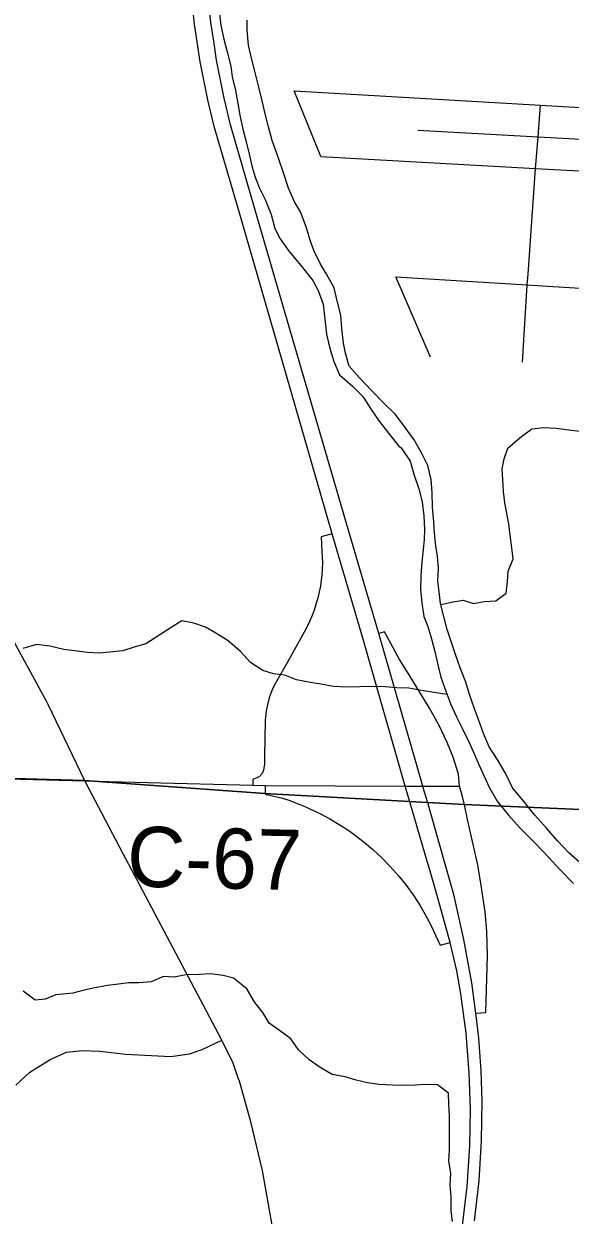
# Model space of a CAD drawing. Extents: x 0 to 34, y 0 to 22.
# Drawn here: x 4.264 to 4.779, y 17.887 to 19.012 of the extents above; entities that cross this region are included whole.
import ezdxf

# ---------------------------------------------------------------- set-up
doc = ezdxf.new("R2010")
doc.units = 0
for name, color, linetype in [('GM_X_City_Street', 7, 'Continuous'), ('GM_X_Corporation', 7, 'Continuous'), ('GM_X_County_Road', 7, 'Continuous'), ('GM_X_County_Road_Text', 7, 'Continuous'), ('GM_X_Interchange_Ramps', 7, 'Continuous'), ('GM_X_Major_River', 7, 'Continuous'), ('GM_X_Minor_River', 7, 'Continuous'), ('GM_X_State_Route', 7, 'Continuous'), ('GM_X_Township_Road', 7, 'Continuous')]:
    doc.layers.add(name, color=color, linetype=linetype)

msp = doc.modelspace()

# ---------------------------------------------------------------- linework, layer by layer
at = {"layer": 'GM_X_City_Street'}
msp.add_lwpolyline([(4.2563, 18.0102), (4.2697, 18.0224), (4.2887, 18.0346), (4.3043, 18.0414), (4.3196, 18.043), (4.3358, 18.0423), (4.36, 18.0395), (4.4028, 18.0374), (4.4204, 18.0399), (4.4321, 18.044), (4.4507, 18.0526)], dxfattribs=at)
at = {"layer": 'GM_X_Corporation'}
for points in [[(8.9341, 20.0965), (4.0253, 20.0965), (4.0048, 19.6179), (3.9989, 19.4811), (3.9958, 19.4084), (3.9927, 19.3361), (3.985, 19.1554), (3.9815, 19.0743), (3.9811, 19.0651), (3.9791, 19.0203), (3.9633, 18.6757), (3.9621, 18.6649), (3.9605, 18.6483), (3.9468, 18.3161), (3.9995, 18.3123), (4.1878, 18.3016), (4.3213, 18.298), (4.4914, 18.2857), (4.6278, 18.2782), (4.6446, 18.2772), (4.6794, 18.2753), (5.2805, 18.2495)], [(5.2805, 18.2495), (4.6794, 18.2753), (4.6446, 18.2772), (4.6278, 18.2782), (4.4914, 18.2857), (4.3213, 18.298), (4.1878, 18.3016), (3.9995, 18.3123), (3.9468, 18.3161), (3.9184, 17.601), (3.9153, 17.5377), (3.8996, 17.2129), (3.8967, 17.1525), (3.8962, 17.1422), (3.892, 17.0557), (3.8892, 16.9991), (3.8746, 16.7014), (3.8519, 16.2289), (3.8392, 15.9277), (3.8357, 15.8507), (3.8186, 15.5835)]]:
    msp.add_lwpolyline(points, dxfattribs=at)
at = {"layer": 'GM_X_County_Road'}
for p, q in [((4.3215, 18.2975), (4.2869, 18.3697)), ((4.3215, 18.2975), (4.3314, 18.2972)), ((4.3314, 18.2972), (4.3809, 18.296)), ((4.6472, 18.2924), (4.6611, 18.2924)), ((4.6611, 18.2924), (4.675, 18.2924))]:
    msp.add_line(p, q, dxfattribs=at)
for points in [[(4.2869, 18.3697), (4.286, 18.3715), (4.2515, 18.4352), (4.224, 18.4898), (4.2171, 18.5041), (4.2112, 18.5231), (4.2021, 18.5636), (4.201, 18.5798), (4.2016, 18.5981), (4.2027, 18.6147), (4.206, 18.6517), (4.2118, 18.803), (4.215, 18.8563), (4.2189, 18.9177), (4.2238, 18.9634), (4.2326, 19.0308), (4.2343, 19.0415)], [(4.0601, 18.3083), (4.188, 18.301), (4.3215, 18.2975)], [(4.3762, 18.1938), (4.3578, 18.2287), (4.3215, 18.2975)], [(4.3809, 18.296), (4.4801, 18.2934), (4.4917, 18.2932), (4.6236, 18.2925), (4.6403, 18.2924), (4.6472, 18.2924)], [(4.4663, 18.0168), (4.4614, 18.0309), (4.4507, 18.0526), (4.3762, 18.1938)], [(4.5078, 17.8236), (4.5074, 17.8265), (4.489, 17.9296), (4.478, 17.9757), (4.4673, 18.014), (4.4663, 18.0168)]]:
    msp.add_lwpolyline(points, dxfattribs=at)
at = {"layer": 'GM_X_Interchange_Ramps'}
for p, q in [((4.5549, 18.5309), (4.5444, 18.5279)), ((4.692, 18.2194), (4.6826, 18.2612))]:
    msp.add_line(p, q, dxfattribs=at)
for points in [[(4.5444, 18.5279), (4.5452, 18.514), (4.5455, 18.509), (4.5456, 18.5036), (4.5454, 18.4976), (4.545, 18.4918), (4.5445, 18.487), (4.5437, 18.4814), (4.5426, 18.4759), (4.5412, 18.4701), (4.5398, 18.4652), (4.5378, 18.4588), (4.5358, 18.4536), (4.5338, 18.4488), (4.5311, 18.4433), (4.5283, 18.4379), (4.5126, 18.4097)], [(4.6668, 18.3252), (4.6633, 18.3337), (4.6558, 18.3498), (4.6467, 18.3663), (4.6276, 18.3977), (4.6183, 18.4123), (4.6042, 18.4382), (4.5988, 18.4367)], [(4.5126, 18.4097), (4.504, 18.3943), (4.5014, 18.3897), (4.499, 18.385), (4.4971, 18.3805), (4.4955, 18.376), (4.494, 18.3706), (4.4929, 18.3652), (4.4923, 18.3609), (4.4919, 18.3576), (4.4917, 18.3544), (4.491, 18.3211), (4.4909, 18.3137), (4.4901, 18.3077), (4.4887, 18.3045), (4.4859, 18.3013), (4.4801, 18.2989), (4.4801, 18.2934)], [(4.675, 18.2924), (4.6741, 18.3039), (4.669, 18.3199), (4.6668, 18.3252)], [(4.4917, 18.2932), (4.4917, 18.2851), (4.5081, 18.2812), (4.5149, 18.2789), (4.5235, 18.2757), (4.5245, 18.2753)], [(4.6826, 18.2612), (4.6796, 18.2748), (4.6777, 18.2827), (4.675, 18.2924)], [(4.5245, 18.2753), (4.5332, 18.2716), (4.5439, 18.2664), (4.5525, 18.2618), (4.5614, 18.2565), (4.5704, 18.2507), (4.5781, 18.2451), (4.5854, 18.2394), (4.5933, 18.2326), (4.6018, 18.2248), (4.6098, 18.2165), (4.6176, 18.2076), (4.6245, 18.199), (4.6318, 18.1889), (4.6375, 18.1801), (4.6438, 18.1692), (4.6483, 18.1606), (4.6566, 18.1425), (4.6661, 18.1448)], [(4.6902, 18.0781), (4.6998, 18.0788), (4.7012, 18.1326), (4.7008, 18.1556), (4.6992, 18.1735), (4.6956, 18.1969), (4.6922, 18.2183), (4.692, 18.2194)]]:
    msp.add_lwpolyline(points, dxfattribs=at)
at = {"layer": 'GM_X_Major_River'}
for points in [[(4.4478, 19.0273), (4.4497, 19.0109), (4.4525, 18.998), (4.4557, 18.9861), (4.4592, 18.9724), (4.4605, 18.9625), (4.4637, 18.9495), (4.4657, 18.9373), (4.4677, 18.9263), (4.4705, 18.913), (4.4733, 18.9023), (4.4768, 18.8882), (4.4793, 18.8771), (4.4821, 18.8675), (4.4861, 18.858), (4.4915, 18.8465), (4.4973, 18.8323), (4.5008, 18.8193), (4.5059, 18.8094), (4.5144, 18.7974), (4.5255, 18.7839), (4.5366, 18.77), (4.5417, 18.7605), (4.5464, 18.7478), (4.548, 18.7334), (4.5496, 18.7193), (4.5524, 18.7071), (4.5563, 18.6937), (4.5617, 18.6811), (4.574, 18.6702), (4.5841, 18.6601), (4.5903, 18.6502), (4.5991, 18.6371), (4.608, 18.6259), (4.6176, 18.6135)], [(4.7912, 18.2179), (4.7782, 18.2296), (4.7674, 18.2408), (4.757, 18.2528), (4.7459, 18.2651), (4.7363, 18.2775), (4.7248, 18.291), (4.719, 18.3036), (4.711, 18.3171), (4.7029, 18.3298), (4.6974, 18.3424), (4.6928, 18.3554), (4.6888, 18.3665), (4.6845, 18.3791), (4.681, 18.3909), (4.6756, 18.4043), (4.6713, 18.4169), (4.6677, 18.4273), (4.6634, 18.4406), (4.6571, 18.4651), (4.6558, 18.4761), (4.6545, 18.486), (4.6551, 18.4981), (4.6542, 18.5096), (4.6525, 18.5195), (4.6512, 18.5316), (4.6507, 18.5423), (4.6494, 18.556), (4.649, 18.5697), (4.6481, 18.5822), (4.6449, 18.5952), (4.6387, 18.6078), (4.6322, 18.6197), (4.6237, 18.6313), (4.6144, 18.6436), (4.6029, 18.6548), (4.5918, 18.6661), (4.5806, 18.6781), (4.571, 18.6893), (4.5675, 18.7015), (4.5654, 18.711), (4.5638, 18.7247), (4.5629, 18.7373), (4.5594, 18.751), (4.5566, 18.7632), (4.5496, 18.7759), (4.5434, 18.7862), (4.5376, 18.7985), (4.534, 18.8081), (4.5304, 18.8207), (4.525, 18.8348), (4.5192, 18.8444), (4.5137, 18.8571), (4.5091, 18.8708), (4.5041, 18.8857), (4.4983, 18.9022), (4.4948, 18.9151), (4.492, 18.9262), (4.4889, 18.9396), (4.4861, 18.9514), (4.4822, 18.9666), (4.4787, 18.98), (4.4759, 18.9922), (4.4747, 19.0063), (4.4745, 19.0158)], [(4.6176, 18.6135), (4.6199, 18.612), (4.6283, 18.5993), (4.6322, 18.5863), (4.6365, 18.5733), (4.6397, 18.5611), (4.6413, 18.5478), (4.6418, 18.5349), (4.6416, 18.5254), (4.6407, 18.5159), (4.6393, 18.5041), (4.6383, 18.4913), (4.638, 18.4784), (4.6393, 18.4658), (4.6413, 18.4528), (4.6449, 18.4433), (4.6485, 18.4318), (4.6516, 18.4196), (4.6547, 18.4059), (4.6572, 18.3956), (4.6619, 18.3822), (4.6669, 18.3696), (4.672, 18.3581), (4.6775, 18.3473), (4.684, 18.3339), (4.6891, 18.3224), (4.6931, 18.3129), (4.6974, 18.3033), (4.7032, 18.291), (4.7106, 18.2783), (4.7209, 18.2656), (4.7324, 18.2525), (4.7465, 18.2385), (4.7588, 18.2254), (4.7699, 18.2134), (4.7825, 18.2006)]]:
    msp.add_lwpolyline(points, dxfattribs=at)
at = {"layer": 'GM_X_Minor_River'}
for points in [[(4.6573, 18.4641), (4.6688, 18.4665), (4.6783, 18.4682), (4.6881, 18.465), (4.6983, 18.4668), (4.7093, 18.4674), (4.7189, 18.4748), (4.7202, 18.4859), (4.7207, 18.4957), (4.7254, 18.5071), (4.7244, 18.5177), (4.7227, 18.5295), (4.7213, 18.5402), (4.7178, 18.56), (4.7164, 18.5707), (4.7158, 18.5821), (4.7152, 18.5923), (4.7169, 18.6018), (4.7204, 18.6116), (4.7319, 18.6214), (4.743, 18.6299), (4.754, 18.6313), (4.7661, 18.6307), (4.7782, 18.629), (4.7885, 18.6277)], [(4.663, 18.3792), (4.6528, 18.3808), (4.6411, 18.3825), (4.6271, 18.385), (4.6157, 18.3855), (4.6048, 18.3865), (4.5945, 18.3866), (4.5809, 18.3864), (4.5691, 18.3859), (4.5562, 18.3868), (4.5441, 18.3889), (4.5343, 18.3905), (4.5211, 18.393), (4.5101, 18.3974), (4.4995, 18.3987), (4.4894, 18.4019), (4.4777, 18.4093), (4.4684, 18.4197), (4.4568, 18.4297), (4.4451, 18.4371), (4.4353, 18.4426), (4.4244, 18.4465), (4.413, 18.4486), (4.402, 18.4419), (4.379, 18.4271), (4.3691, 18.4242), (4.3573, 18.4202), (4.3452, 18.4192), (4.3349, 18.4182), (4.3239, 18.4188), (4.3118, 18.4205), (4.3016, 18.4217), (4.2884, 18.4246), (4.2759, 18.4263), (4.263, 18.4227)], [(4.6672, 17.9048), (4.6662, 17.9162), (4.6667, 17.9268), (4.665, 17.9386), (4.6655, 17.9489), (4.6656, 17.9595), (4.6654, 17.9705), (4.6656, 17.9808), (4.665, 17.9922), (4.6647, 18.0028), (4.6542, 18.0106), (4.6428, 18.0108), (4.633, 18.0102), (4.6224, 18.0099), (4.6118, 18.0101), (4.5992, 18.0107), (4.5883, 18.0123), (4.5773, 18.0148), (4.5671, 18.018), (4.5547, 18.0204), (4.5426, 18.0275), (4.5329, 18.0344), (4.5231, 18.0437), (4.5157, 18.0541), (4.5052, 18.0618), (4.4954, 18.0688), (4.4895, 18.0788), (4.482, 18.0884), (4.4743, 18.1011), (4.4619, 18.1111), (4.4521, 18.1139), (4.44, 18.1153), (4.4297, 18.1147), (4.4168, 18.1145), (4.4058, 18.1123), (4.3956, 18.1129), (4.3841, 18.1077), (4.3724, 18.1068), (4.3629, 18.1069), (4.3534, 18.1055), (4.3428, 18.1042), (4.3295, 18.1017), (4.3196, 18.0996), (4.3101, 18.097), (4.2941, 18.0954), (4.2842, 18.0914), (4.2747, 18.0904), (4.2635, 18.0989)], [(4.6684, 17.8815), (4.667, 17.8918), (4.6672, 17.9048)]]:
    msp.add_lwpolyline(points, dxfattribs=at)
at = {"layer": 'GM_X_State_Route'}
for points in [[(4.5549, 18.5309), (4.5111, 18.6826), (4.4664, 18.837), (4.4436, 18.9155), (4.4376, 18.9407), (4.4304, 18.9765), (4.4251, 19.0122), (4.4218, 19.0409), (4.4203, 19.0712), (4.4194, 19.0958), (4.4194, 19.1245), (4.4201, 19.1598), (4.4341, 19.416), (4.4387, 19.5226), (4.4504, 19.7346), (4.453, 19.8068), (4.4508, 19.8691), (4.4482, 19.9018)], [(4.4431, 18.9959), (4.4405, 19.0138), (4.4372, 19.0426), (4.4357, 19.0728), (4.4348, 19.0974), (4.4348, 19.1261), (4.4372, 19.1632), (4.4373, 19.1652), (4.4439, 19.2954)], [(4.6419, 18.2869), (4.6403, 18.2924), (4.5988, 18.4367), (4.5699, 18.5352), (4.5265, 18.6842), (4.4817, 18.8386), (4.4589, 18.9171), (4.453, 18.9423), (4.4458, 18.9781), (4.4431, 18.9959)], [(4.6448, 18.2206), (4.628, 18.2776), (4.6236, 18.2925), (4.5837, 18.4323), (4.5549, 18.5309)], [(4.6609, 18.2212), (4.6449, 18.2767), (4.6419, 18.2869)], [(4.6661, 18.1448), (4.6547, 18.1859), (4.6459, 18.2168), (4.6448, 18.2206)], [(4.689, 17.8821), (4.6934, 17.9198), (4.6958, 17.9575), (4.6962, 17.9953), (4.6954, 18.0238), (4.6932, 18.0547), (4.6902, 18.0781), (4.6866, 18.1069), (4.6791, 18.1479), (4.6697, 18.1902), (4.6609, 18.2212)], [(4.6776, 17.8776), (4.682, 17.9144), (4.6848, 17.9528), (4.6853, 17.9875), (4.684, 18.0217), (4.6811, 18.0594), (4.6763, 18.0963), (4.6723, 18.1182), (4.6661, 18.1448)]]:
    msp.add_lwpolyline(points, dxfattribs=at)
at = {"layer": 'GM_X_Township_Road'}
for p, q in [((4.5441, 18.887), (4.5191, 18.949)), ((4.6476, 18.6975), (4.615, 18.7736)), ((4.7578, 18.7648), (5.2534, 18.7343))]:
    msp.add_line(p, q, dxfattribs=at)
for points in [[(4.5191, 18.949), (4.7513, 18.9355), (4.8051, 18.9324), (5.0861, 18.9177), (5.2083, 18.9113), (5.2692, 18.9081)], [(4.7396, 18.7759), (4.7467, 18.8758), (4.749, 18.9058), (4.7513, 18.9355)], [(4.6356, 18.912), (4.749, 18.9058), (5.0846, 18.8874), (5.2019, 18.8809)], [(4.5441, 18.887), (4.7467, 18.8758), (5.0832, 18.8578), (5.1957, 18.8517), (5.2673, 18.8481)], [(4.7343, 18.6929), (4.7389, 18.7659), (4.7396, 18.7759)], [(4.615, 18.7736), (4.7389, 18.7659), (4.7484, 18.7653), (4.7578, 18.7648)]]:
    msp.add_lwpolyline(points, dxfattribs=at)

# ---------------------------------------------------------------- texts
at = {"layer": 'GM_X_County_Road_Text'}
msp.add_text('C-67', height=0.05682, rotation=358.775, dxfattribs=at).set_placement((4.3609, 18.1979))

doc.saveas('drawing.dxf')
